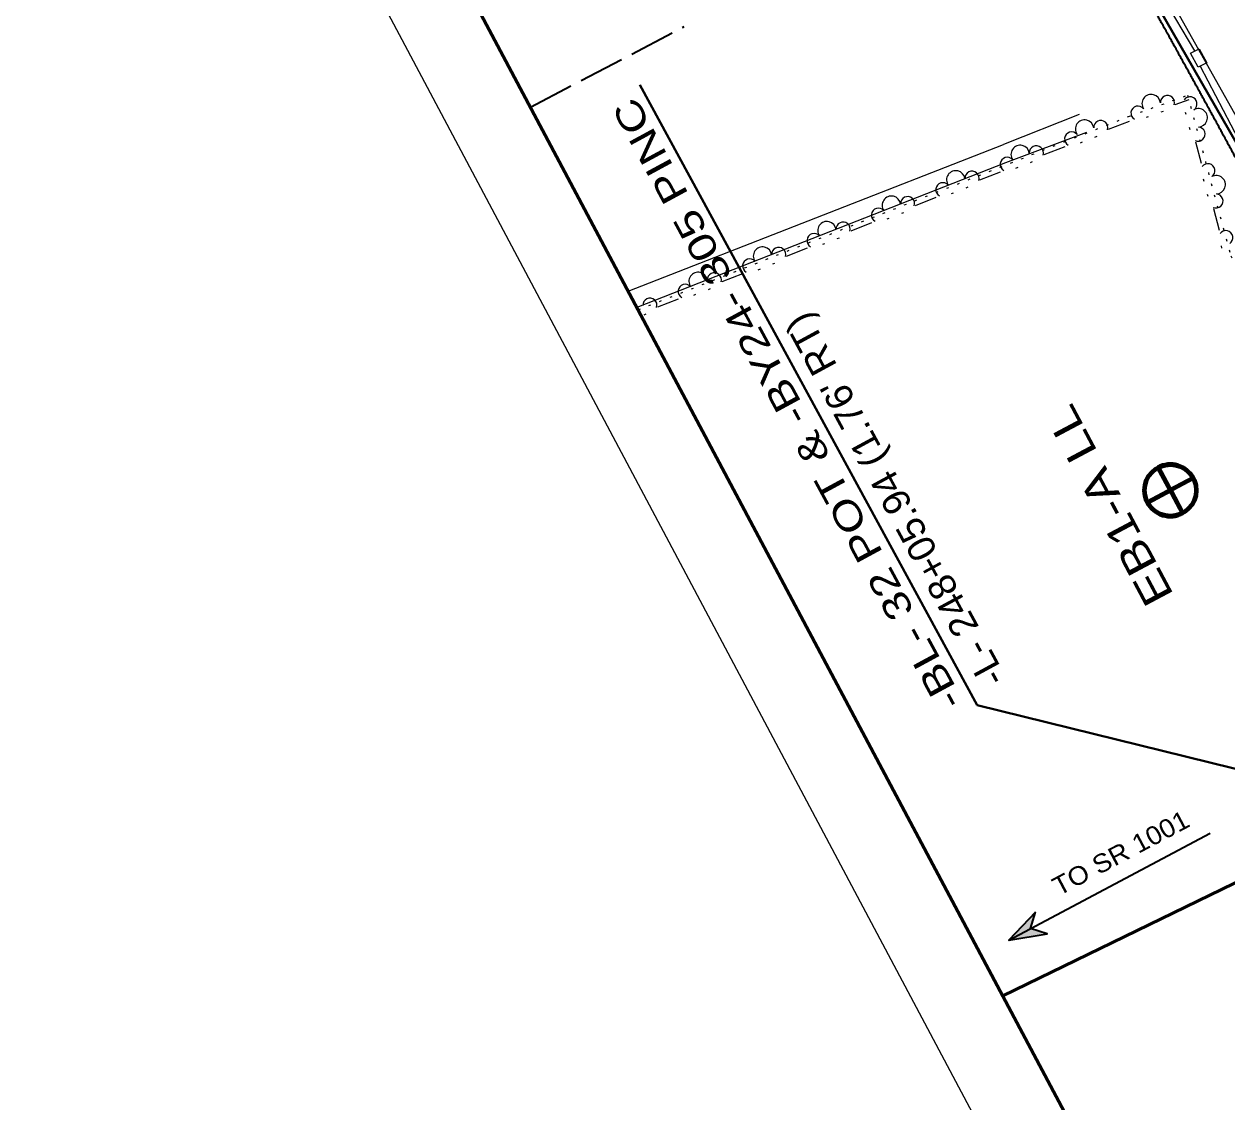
# Model space of a CAD drawing. Extents: x 2402199 to 2404507, y 568050 to 571478.
# Drawn here: x 2402199.5 to 2402420.4, y 570914.9 to 571112.8 of the extents above; entities that cross this region are included whole.
import ezdxf
from ezdxf.enums import TextEntityAlignment as Align

# ---------------------------------------------------------------- set-up
doc = ezdxf.new("R2010")
doc.units = 0
doc.header["$LTSCALE"] = 1.4
for name, pattern in [('DOTTED', [1.5, 0.3, -1.2]), ('LONG_DASHED', [7.5, 6, -1.5]), ('MEDIUM_DASHED', [4.5, 3, -1.5])]:
    doc.linetypes.add(name, pattern=pattern)
for name, color, linetype, lineweight in [('1', 7, 'Continuous', 35), ('10', 7, 'Continuous', 25), ('11', 7, 'Continuous', 25), ('15', 7, 'DOTTED', 40), ('17', 7, 'MEDIUM_DASHED', 35), ('21', 7, 'Continuous', 40), ('27', 7, 'Continuous', 80), ('28', 7, 'Continuous', 25), ('3', 7, 'Continuous', 25), ('6', 7, 'Continuous', 35), ('62', 7, 'Continuous', 60), ('63', 7, 'Continuous', 35)]:
    doc.layers.add(name, color=color, linetype=linetype, lineweight=lineweight)
doc.layers.add('23', color=7, linetype='Continuous')

msp = doc.modelspace()

# ---------------------------------------------------------------- hatches: boundary and pattern name
at = {"layer": '10'}
msp.add_hatch(color=256, dxfattribs=at).paths.add_polyline_path([(2402385.229, 570949.774), (2402380.325, 570944.618), (2402387.341, 570945.801), (2402384.299, 570946.731)])

# ---------------------------------------------------------------- linework, layer by layer
at = {"layer": '1'}
for points in [[(2402414.666, 571101.586), (2402414.237, 571102.366), (2402413.803, 571103.154), (2402413.373, 571103.933), (2402412.944, 571104.713), (2402412.514, 571105.491), (2402412.084, 571106.271), (2402411.654, 571107.049), (2402411.223, 571107.828), (2402410.792, 571108.606), (2402410.361, 571109.385), (2402409.93, 571110.163), (2402409.498, 571110.941), (2402409.061, 571111.727), (2402408.629, 571112.505), (2402408.197, 571113.283), (2402407.765, 571114.06), (2402407.332, 571114.838), (2402406.899, 571115.615), (2402406.466, 571116.392), (2402406.032, 571117.169), (2402405.598, 571117.946), (2402405.165, 571118.723), (2402404.73, 571119.499), (2402404.296, 571120.276), (2402403.856, 571121.061), (2402403.422, 571121.837), (2402402.986, 571122.613), (2402402.551, 571123.39), (2402402.115, 571124.165), (2402401.68, 571124.941), (2402401.243, 571125.716), (2402400.806, 571126.492), (2402400.37, 571127.267), (2402399.933, 571128.042), (2402399.496, 571128.817), (2402399.053, 571129.601), (2402398.616, 571130.375), (2402398.178, 571131.15), (2402397.74, 571131.924), (2402397.302, 571132.699), (2402396.863, 571133.473), (2402396.424, 571134.247), (2402395.985, 571135.021), (2402395.546, 571135.795), (2402395.106, 571136.569), (2402394.666, 571137.342), (2402394.221, 571138.124), (2402393.781, 571138.897), (2402393.34, 571139.671), (2402392.9, 571140.443), (2402392.459, 571141.216), (2402392.018, 571141.989), (2402391.576, 571142.761), (2402391.134, 571143.534), (2402390.692, 571144.306), (2402390.25, 571145.079), (2402389.808, 571145.851), (2402389.36, 571146.631), (2402388.916, 571147.403), (2402388.474, 571148.174), (2402388.03, 571148.946), (2402387.586, 571149.718), (2402387.143, 571150.489), (2402386.698, 571151.26), (2402386.254, 571152.031), (2402385.809, 571152.802), (2402385.365, 571153.572), (2402384.919, 571154.343), (2402384.469, 571155.122), (2402384.023, 571155.892), (2402383.577, 571156.662), (2402383.131, 571157.432), (2402382.238, 571158.973)], [(2402445.746, 571043.492), (2402445.335, 571044.281), (2402444.925, 571045.069), (2402444.513, 571045.858), (2402444.102, 571046.647), (2402443.691, 571047.436), (2402443.279, 571048.224), (2402442.867, 571049.012), (2402442.454, 571049.8), (2402442.041, 571050.588), (2402441.624, 571051.385), (2402441.211, 571052.172), (2402440.797, 571052.96), (2402440.384, 571053.748), (2402439.97, 571054.535), (2402439.556, 571055.322), (2402439.142, 571056.109), (2402438.727, 571056.897), (2402438.312, 571057.684), (2402437.897, 571058.47), (2402437.482, 571059.257), (2402437.062, 571060.052), (2402436.646, 571060.838), (2402436.23, 571061.624), (2402435.813, 571062.41), (2402435.397, 571063.196), (2402434.98, 571063.983), (2402434.563, 571064.768), (2402434.146, 571065.554), (2402433.728, 571066.339), (2402433.311, 571067.125), (2402432.893, 571067.91), (2402432.47, 571068.703), (2402432.051, 571069.488), (2402431.632, 571070.273), (2402431.213, 571071.058), (2402430.794, 571071.843), (2402430.374, 571072.627), (2402429.954, 571073.411), (2402429.535, 571074.196), (2402429.114, 571074.98), (2402428.694, 571075.764), (2402428.273, 571076.547), (2402427.848, 571077.34), (2402427.426, 571078.123), (2402427.005, 571078.906), (2402426.583, 571079.69), (2402426.161, 571080.473), (2402425.739, 571081.256), (2402425.316, 571082.039), (2402424.894, 571082.822), (2402424.471, 571083.604), (2402424.047, 571084.387), (2402423.624, 571085.169), (2402423.195, 571085.96), (2402422.771, 571086.742), (2402422.347, 571087.524), (2402421.923, 571088.306), (2402421.498, 571089.088), (2402421.073, 571089.87), (2402420.648, 571090.651), (2402420.223, 571091.432), (2402419.797, 571092.214), (2402419.371, 571092.995), (2402418.945, 571093.775), (2402418.514, 571094.565), (2402418.087, 571095.346), (2402417.66, 571096.126), (2402417.233, 571096.907), (2402416.806, 571097.687), (2402416.378, 571098.467), (2402415.95, 571099.247), (2402415.522, 571100.027), (2402415.094, 571100.807), (2402414.665, 571101.587)]]:
    msp.add_spline(points, degree=3, dxfattribs=at)
at = {"layer": '10'}
for p, q in [((2402393.21, 571096.219), (2402379.347, 571090.663)), ((2402394.572, 571092.879), (2402379.688, 571087.325)), ((2402310.424, 571063.757), (2402379.347, 571090.663)), ((2402379.688, 571087.325), (2402312.006, 571060.782))]:
    msp.add_line(p, q, dxfattribs=at)
at = {"layer": '10', "lineweight": 35}
msp.add_lwpolyline([(2402385.229, 570949.774), (2402380.325, 570944.618), (2402387.341, 570945.801), (2402384.299, 570946.731)], close=True, dxfattribs=at)
at = {"layer": '11'}
for p, q in [((2402410.854, 571098.033), (2402413.407, 571098.953)), ((2402405.592, 571095.701), (2402405.977, 571095.839)), ((2402408.293, 571096.674), (2402408.679, 571096.814)), ((2402412.685, 571096.633), (2402412.791, 571096.236)), ((2402398.632, 571093.489), (2402402.447, 571094.993)), ((2402413.429, 571093.862), (2402413.535, 571093.466)), ((2402396.113, 571092.056), (2402396.494, 571092.206)), ((2402386.803, 571088.829), (2402390.619, 571090.333)), ((2402393.441, 571091.003), (2402393.823, 571091.154)), ((2402414.569, 571091.194), (2402415.633, 571087.234)), ((2402384.282, 571087.395), (2402384.663, 571087.544)), ((2402374.975, 571084.169), (2402378.791, 571085.672)), ((2402381.61, 571086.342), (2402381.992, 571086.492)), ((2402372.454, 571082.734), (2402372.835, 571082.884)), ((2402415.981, 571084.354), (2402416.088, 571083.958)), ((2402363.147, 571079.508), (2402366.962, 571081.012)), ((2402369.782, 571081.682), (2402370.164, 571081.832)), ((2402416.725, 571081.581), (2402416.832, 571081.184)), ((2402360.626, 571078.074), (2402361.007, 571078.224)), ((2402417.865, 571078.916), (2402418.928, 571074.955)), ((2402351.319, 571074.848), (2402355.134, 571076.351)), ((2402357.953, 571077.021), (2402358.336, 571077.171)), ((2402339.49, 571070.187), (2402343.306, 571071.691)), ((2402346.127, 571072.361), (2402346.508, 571072.511)), ((2402348.797, 571073.413), (2402349.179, 571073.563)), ((2402419.277, 571072.078), (2402419.383, 571071.682)), ((2402334.299, 571067.701), (2402334.68, 571067.851)), ((2402336.969, 571068.753), (2402337.351, 571068.903)), ((2402327.662, 571065.527), (2402331.478, 571067.03)), ((2402322.473, 571063.04), (2402322.854, 571063.191)), ((2402325.141, 571064.092), (2402325.522, 571064.243)), ((2402315.834, 571060.866), (2402319.649, 571062.369)), ((2402313.315, 571059.432), (2402313.697, 571059.583))]:
    msp.add_line(p, q, dxfattribs=at)
at = {"layer": '11', "linetype": 'DOTTED'}
msp.add_line((2402312.245, 571060.333), (2402402.474, 571095.885), dxfattribs=at)
msp.add_lwpolyline([(2402402.474, 571095.885), (2402413.129, 571099.725), (2402421.048, 571070.224), (2402472.559, 570975.083)], dxfattribs=at)
at = {"layer": '11'}
for centre, radius, start, end in [((2402406.44, 571098.186), 1.691, 5.78059, 213.85308), ((2402409.419, 571098.388), 1.297, 340.58532, 181.38189), ((2402413.554, 571098.14), 1.297, 303.46121, 144.25778), ((2402404.017, 571096.441), 1.297, 38.25179, 239.04836), ((2402415.09, 571095.58), 1.691, 270.99002, 119.06251), ((2402394.214, 571093.512), 1.691, 7.46916, 215.54165), ((2402397.186, 571093.801), 1.297, 342.27389, 183.07046), ((2402415.043, 571092.595), 1.297, 245.79474, 86.59131), ((2402391.844, 571091.697), 1.297, 39.94036, 240.73693), ((2402382.386, 571088.852), 1.691, 7.46916, 215.54165), ((2402385.358, 571089.141), 1.297, 342.27389, 183.07046), ((2402380.016, 571087.036), 1.297, 39.94036, 240.73693), ((2402416.85, 571085.862), 1.297, 303.46121, 144.25778), ((2402370.558, 571084.191), 1.691, 7.46916, 215.54165), ((2402373.529, 571084.48), 1.297, 342.27389, 183.07046), ((2402418.387, 571083.302), 1.691, 270.99002, 119.06251), ((2402368.188, 571082.376), 1.297, 39.94036, 240.73693), ((2402358.73, 571079.531), 1.691, 7.46916, 215.54165), ((2402361.701, 571079.82), 1.297, 342.27389, 183.07046), ((2402418.339, 571080.317), 1.297, 245.79474, 86.59131), ((2402356.36, 571077.715), 1.297, 39.94036, 240.73693), ((2402346.902, 571074.87), 1.691, 7.46916, 215.54165), ((2402349.873, 571075.159), 1.297, 342.27389, 183.07046), ((2402344.531, 571073.055), 1.297, 39.94036, 240.73693), ((2402420.146, 571073.583), 1.297, 303.46121, 144.25778), ((2402335.073, 571070.21), 1.691, 7.46916, 215.54165), ((2402338.045, 571070.499), 1.297, 342.27389, 183.07046), ((2402332.703, 571068.394), 1.297, 39.94036, 240.73693), ((2402323.245, 571065.549), 1.691, 7.46916, 215.54165), ((2402326.217, 571065.838), 1.297, 342.27389, 183.07046), ((2402320.875, 571063.734), 1.297, 39.94036, 240.73693), ((2402314.389, 571061.178), 1.297, 342.27389, 183.07046)]:
    msp.add_arc(centre, radius, start, end, dxfattribs=at)
at = {"layer": '15'}
msp.add_arc((2399911.332, 569690.208), 2887.133, 22.84472, 37.57762, dxfattribs=at)
at = {"layer": '17', "linetype": 'LONG_DASHED'}
msp.add_line((2402292.456, 571097.55), (2402320.706, 571112.334), dxfattribs=at)
at = {"layer": '21'}
msp.add_line((2402453.011, 570968.339), (2402374.495, 570987.785), dxfattribs=at)
msp.add_lwpolyline([(2402571.932, 570780.533), (2402538.299, 570859.007), (2402503.143, 570934.851), (2402464.804, 571011.777), (2402426.113, 571084.024), (2402384.214, 571156.832), (2402372.534, 571175.865)], dxfattribs=at)
at = {"layer": '27'}
for p, q in [((2402407.742, 571031.383), (2402412.195, 571023.007)), ((2402414.157, 571029.421), (2402405.78, 571024.969)), ((2402405.755, 571025.015), (2402405.78, 571024.969))]:
    msp.add_line(p, q, dxfattribs=at)
at = {"layer": '27', "lineweight": 35}
msp.add_line((2402380.325, 570944.618), (2402417.248, 570964.25), dxfattribs=at)
at = {"layer": '27'}
for points in [[(2402414.157, 571029.421), (2402409.968, 571027.196), (2402407.742, 571031.383), (2402407.695, 571031.358)], [(2402405.78, 571024.969), (2402409.968, 571027.196), (2402412.195, 571023.007)]]:
    msp.add_lwpolyline(points, dxfattribs=at)
msp.add_circle((2402409.968, 571027.195), 4.743, dxfattribs=at)
for start, end in [(28, 118.64427), (207.35574, 298)]:
    msp.add_arc((2402409.968, 571027.195), 4.743, start, end, dxfattribs=at)
at = {"layer": '28'}
msp.add_lwpolyline([(2402374.812, 571177.076), (2402399.705, 571135.603), (2402440.232, 571063.522), (2402479.967, 570987.625), (2402515.512, 570914.776), (2402552.113, 570833.795), (2402574.37, 570781.072)], dxfattribs=at)
at = {"layer": '3'}
msp.add_lwpolyline([(2402374.812, 571177.076), (2402399.705, 571135.603), (2402440.232, 571063.522), (2402479.967, 570987.625), (2402515.512, 570914.776), (2402552.113, 570833.795), (2402574.37, 570781.072)], dxfattribs=at)
at = {"layer": '6', "lineweight": 13}
for p, q in [((2402373.595, 571177.375), (2402414.387, 571107.848)), ((2402415.453, 571105.055), (2402511.71, 570919.872))]:
    msp.add_line(p, q, dxfattribs=at)
at = {"layer": '6', "lineweight": 25}
msp.add_lwpolyline([(2402415.226, 571108.265), (2402416.632, 571105.705), (2402415.093, 571104.86), (2402413.688, 571107.42)], close=True, dxfattribs=at)
at = {"layer": '62'}
msp.add_line((2402379.217, 570934.377), (2402649.132, 571065.756), dxfattribs=at)
msp.add_arc((2399929.798, 569697.989), 2887.133, 22.84477, 31.13893, dxfattribs=at)
at = {"layer": '63', "lineweight": 13}
msp.add_line((2402247.375, 571150.383), (2402486.806, 570700.08), dxfattribs=at)
at = {"layer": '63', "lineweight": 60}
msp.add_line((2402492.519, 570721.286), (2402266.253, 571146.83), dxfattribs=at)
at = {"layer": '63', "lineweight": 40}
msp.add_line((2402374.495, 570987.785), (2402312.546, 571101.626), dxfattribs=at)

# ---------------------------------------------------------------- texts
at = {"layer": '1'}
for s, width, p in [('-BL- 32 POT & -BY24- 305 PINC', 1.3, (2402372.036, 570988.502)), ("-L- 248+05.94 (1.76' RT)", 1.05, (2402379.948, 570992.792))]:
    msp.add_text(s, height=5, rotation=118.473, dxfattribs=dict(at, width=width)).set_placement(p)
at = {"layer": '23', "width": 1.1}
msp.add_text('TO SR 1001', height=3.375, rotation=28, dxfattribs=at).set_placement((2402401.645, 570959.145), align=Align.CENTER)
at = {"layer": '27', "width": 1.25}
msp.add_text('EB1-A LL', height=5.625, rotation=118, dxfattribs=at).set_placement((2402401.236, 571025.704), align=Align.CENTER)

doc.saveas('drawing.dxf')
